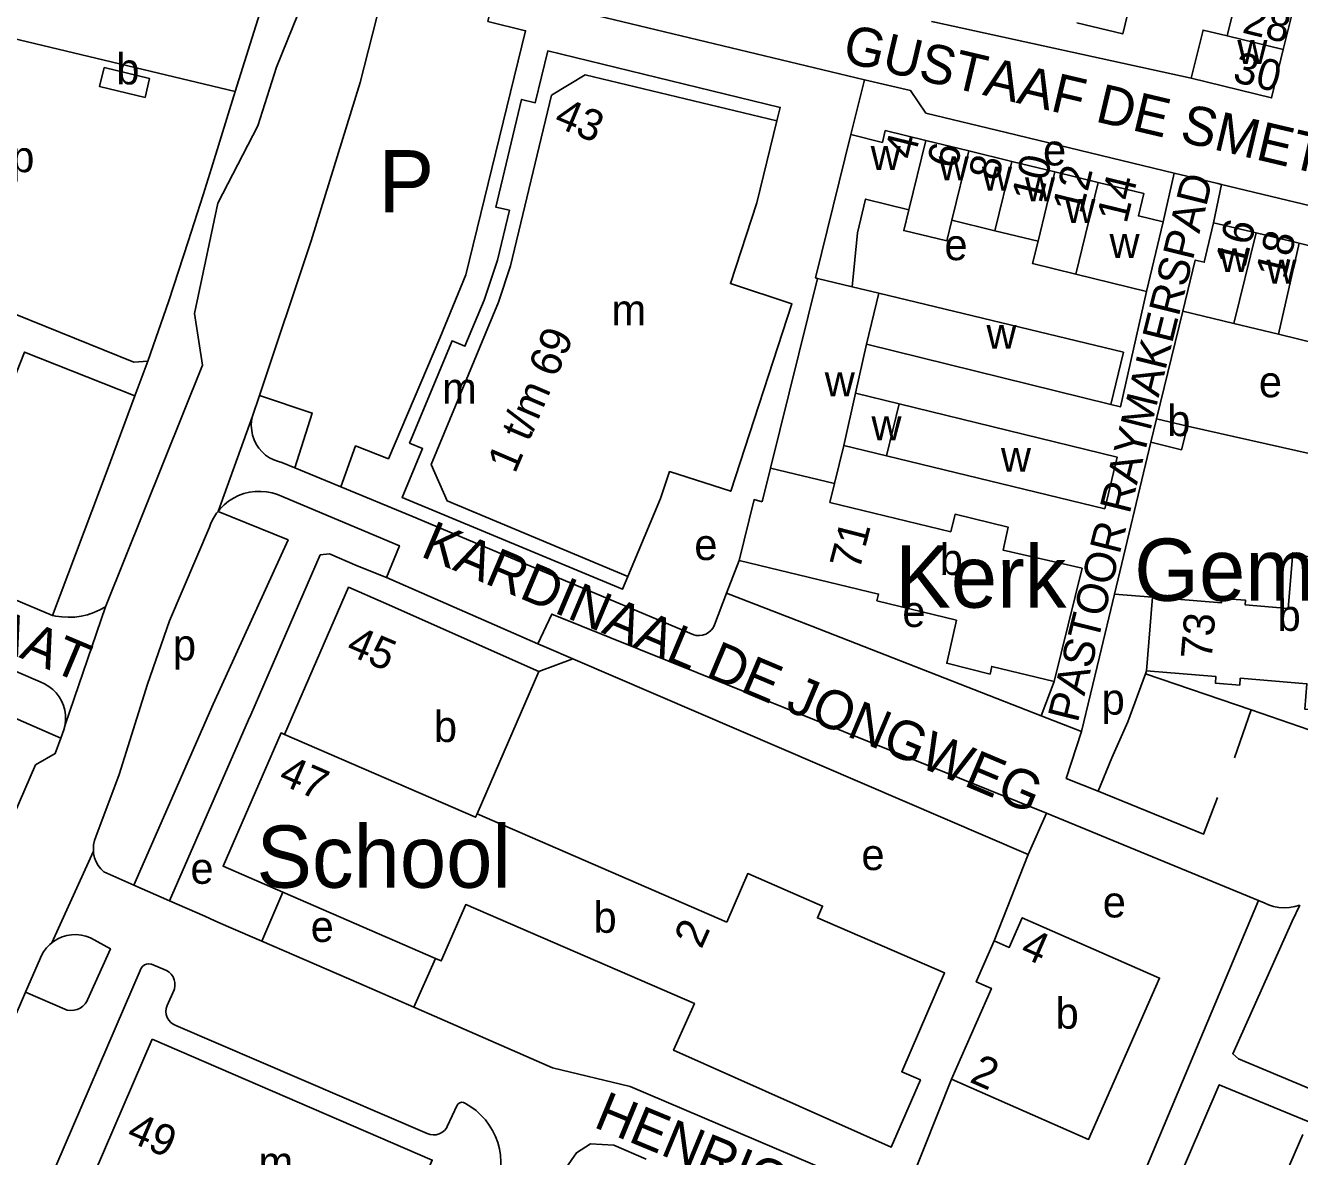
# Model space of a CAD drawing. Extents: x 162804 to 165059, y 381530 to 382901.
# Drawn here: x 163445.8 to 163609.5, y 381960.8 to 382106.1 of the extents above; entities that cross this region are included whole.
import ezdxf

# ---------------------------------------------------------------- set-up
doc = ezdxf.new("R2010")
doc.units = 0
for name, color, linetype in [('BLT_Basislijn', 7, 'Continuous'), ('BLT_Bebouwing', 7, 'Continuous'), ('BLT_Bebouwing_beschrifting', 7, 'Continuous'), ('BLT_Centroide', 7, 'Continuous'), ('BLT_Huisnummer', 7, 'Continuous'), ('BLT_Huisnummer_ tussenligend', 7, 'Continuous'), ('BLT_Huisnummer_reeks', 7, 'Continuous'), ('BLT_Onderdoorgang_en_onderverdeling', 7, 'Continuous'), ('BLT_Onderverdeling_panden', 7, 'Continuous'), ('BLT_Straatnaam', 7, 'Continuous'), ('BLT_Straatnaam_verkleind', 7, 'Continuous'), ('BLT_Tekst_parkeren', 7, 'Continuous'), ('BLT_Vlakafsluiter', 7, 'Continuous')]:
    doc.layers.add(name, color=color, linetype=linetype)

msp = doc.modelspace()

# ---------------------------------------------------------------- linework, layer by layer
at = {"layer": 'BLT_Basislijn'}
for p, q in [((163476.1, 382108.36), (163472.75, 382097.61)), ((163553.62, 382099.14), (163517.21, 382107.85)), ((163432.58, 382107.21), (163472.75, 382097.61)), ((163553.62, 382099.14), (163551.85, 382092.11)), ((163472.75, 382097.61), (163469.68, 382087.77)), ((163469.68, 382087.77), (163468.62, 382084.33)), ((163593.42, 382087.15), (163592.01, 382080.87)), ((163599.5, 382085.69), (163598.5, 382080.75)), ((163468.62, 382084.33), (163466.68, 382078.33)), ((163594.54, 382069.39), (163591.15, 382055.58)), ((163461.51, 382062.99), (163459.84, 382058.5)), ((163474.97, 382055.92), (163475.85, 382058.56)), ((163595.14, 382054.6), (163659.51, 382040.2)), ((163585.76, 382033.03), (163590.42, 382052.56)), ((163478.72, 382049.96), (163480.39, 382049.27)), ((163480.39, 382049.27), (163486.32, 382046.81)), ((163486.32, 382046.81), (163495.44, 382043.03)), ((163531.67, 382027.81), (163495.44, 382043.03)), ((163447.67, 382021.74), (163404.98, 382040.15)), ((163537.52, 382037.37), (163535.89, 382033.15)), ((163492.17, 382035.15), (163511.62, 382026.66)), ((163534.35, 382029.08), (163535.89, 382033.15)), ((163583.84, 382024.98), (163585.76, 382033.03)), ((163590.65, 382032.63), (163585.76, 382033.03)), ((163511.75, 382023.1), (163516.13, 382024.71)), ((163516.13, 382024.71), (163574.65, 381999.55)), ((163583.84, 382024.98), (163581.52, 382015.38)), ((163603.34, 382018.17), (163589.74, 382022.79)), ((163578.02, 382021.79), (163576.32, 382017.41)), ((163469.89, 382018.89), (163459.71, 381995.63)), ((163441.79, 382018.23), (163450.32, 382014.5)), ((163576.32, 382017.41), (163581.52, 382015.38)), ((163601.19, 382011.98), (163603.34, 382018.17)), ((163603.34, 382018.17), (163616.28, 382013.68)), ((163474.46, 382016.89), (163464.28, 381993.61)), ((163574.65, 381999.55), (163577.01, 382004.89)), ((163604.25, 381993.64), (163577.01, 382004.89)), ((163574.65, 381999.55), (163570.29, 381988.48)), ((163455.87, 381997.33), (163459.71, 381995.63)), ((163459.71, 381995.63), (163464.28, 381993.61)), ((163478.86, 381994.73), (163476.15, 381988.43)), ((163468.82, 381991.63), (163464.28, 381993.61)), ((163583.47, 381944.21), (163604.25, 381993.64)), ((163604.98, 381993.34), (163604.25, 381993.64)), ((163447.7, 381986.28), (163445.79, 381981.86)), ((163498.48, 381986.21), (163495.7, 381979.97)), ((163460.67, 381984.96), (163446.05, 381951.14)), ((163462, 381985.46), (163463.89, 381984.65)), ((163445.79, 381981.86), (163437.52, 381962.79)), ((163451.14, 381979.58), (163445.79, 381981.86)), ((163464.89, 381982.19), (163463.98, 381980.16)), ((163465.11, 381977.59), (163497.4, 381963.72)), ((163564.81, 381970.7), (163558.49, 381954.86)), ((163501.25, 381967.34), (163500, 381964.6))]:
    msp.add_line(p, q, dxfattribs=at)
for points in [[(163461.51, 382062.99), (163459.69, 382062.86), (163421.54, 382078.27), (163432.84, 382130.7), (163443.64, 382128.25), (163444.42, 382128.06), (163445.13, 382121.86)], [(163485.62, 382119.81), (163484.97, 382117.94), (163478.04, 382100.76), (163475.63, 382093.22), (163470.51, 382083.28), (163467.5, 382069.11), (163468.55, 382062.47), (163456.05, 382031.42)], [(163475.85, 382058.56), (163482.49, 382078.45), (163488.81, 382098.8), (163491.46, 382109.2)], [(163506.09, 382110.56), (163505.23, 382106.64), (163510.06, 382105.43), (163502.37, 382074.08), (163499.06, 382065.94), (163492.43, 382050.42), (163488.21, 382052.07), (163486.32, 382046.81)], [(163595.63, 382099.32), (163562.66, 382106.52), (163562.25, 382106.63)], [(163561.52, 382094.83), (163559.54, 382097.75), (163553.62, 382099.14)], [(163561.52, 382094.83), (163571.85, 382092.36), (163593.42, 382087.15)], [(163599.5, 382085.69), (163599.05, 382085.8), (163593.42, 382087.15)], [(163599.5, 382085.69), (163664.71, 382070.05), (163665.99, 382068.94), (163665.83, 382067.16), (163664.99, 382063.08)], [(163466.68, 382078.33), (163464.22, 382070.74), (163461.51, 382062.99)], [(163589.88, 382071.94), (163586.55, 382057.11), (163585.27, 382057.42)], [(163413.44, 382065.06), (163441.5, 382053.69), (163445.66, 382064.13), (163459.84, 382058.5)], [(163411.46, 382060.73), (163407.59, 382051.95), (163407.84, 382049.46), (163408.46, 382048.23), (163411.27, 382046.47), (163416.75, 382043.99), (163449.25, 382030.27)], [(163459.84, 382058.5), (163456.28, 382048.91), (163449.25, 382030.27)], [(163475.85, 382058.56), (163482.64, 382056.29), (163480.39, 382049.27)], [(163474.97, 382055.92), (163474.85, 382055.31), (163474.81, 382054.69), (163474.86, 382054.07), (163474.98, 382053.46), (163475.17, 382052.87), (163475.44, 382052.31), (163475.78, 382051.8), (163476.19, 382051.32), (163476.65, 382050.91), (163477.16, 382050.56), (163477.71, 382050.28), (163478.3, 382050.07), (163478.72, 382049.96)], [(163478.18, 382045.82), (163477.48, 382046.04), (163476.76, 382046.18), (163476.03, 382046.24), (163475.3, 382046.22), (163474.57, 382046.13), (163473.86, 382045.95), (163473.17, 382045.7), (163472.51, 382045.38), (163471.89, 382044.98), (163471.32, 382044.52), (163470.8, 382044), (163470.53, 382043.66)], [(163478.18, 382045.82), (163493.84, 382039.24), (163492.17, 382035.15)], [(163470.53, 382043.66), (163470.34, 382043.43), (163469.95, 382042.81), (163469.62, 382042.15), (163469.43, 382041.65)], [(163469.89, 382018.89), (163479.53, 382039.99), (163470.53, 382043.66)], [(163454.82, 382001.85), (163457.83, 382009.84), (163461.45, 382021.45), (163464.31, 382029.59), (163469.43, 382041.65)], [(163492.17, 382035.15), (163488.4, 382036.68), (163484.86, 382038.19), (163483.68, 382038.08), (163474.74, 382017.52), (163474.46, 382016.89)], [(163535.89, 382033.15), (163546.85, 382028.9), (163576.32, 382017.41)], [(163456.05, 382031.42), (163455.32, 382031.01), (163454.56, 382030.66), (163453.76, 382030.39), (163452.95, 382030.2), (163452.12, 382030.09), (163451.28, 382030.05), (163450.44, 382030.1), (163449.68, 382030.19), (163449.25, 382030.27)], [(163577.01, 382004.89), (163513.42, 382030.47), (163511.62, 382026.66)], [(163534.35, 382029.08), (163534.16, 382028.71), (163533.9, 382028.38), (163533.58, 382028.11), (163533.22, 382027.9), (163532.82, 382027.77), (163532.41, 382027.71), (163531.99, 382027.73), (163531.67, 382027.81)], [(163511.62, 382026.66), (163512.75, 382026.17), (163516.13, 382024.71)], [(163589.74, 382022.79), (163587.49, 382016.62), (163585.43, 382012.01), (163583.65, 382007.69)], [(163589.74, 382022.79), (163589.88, 382023.18)], [(163447.67, 382021.74), (163448.24, 382021.49), (163448.78, 382021.17), (163449.28, 382020.79), (163449.72, 382020.34), (163450.11, 382019.85), (163450.42, 382019.3), (163450.67, 382018.73), (163450.84, 382018.12), (163450.93, 382017.5), (163450.94, 382016.88), (163450.87, 382016.25)], [(163450.87, 382016.25), (163450.71, 382015.58)], [(163450.32, 382014.5), (163449.61, 382012.54), (163447.08, 382011.09), (163442.21, 382000)], [(163450.71, 382015.58), (163450.32, 382014.5)], [(163583.65, 382007.69), (163579.56, 382009.35), (163581.52, 382015.38)], [(163599.02, 382006.9), (163597.21, 382002.19), (163583.65, 382007.69)], [(163454.52, 381999.98), (163454.53, 382000.82), (163454.64, 382001.36), (163454.82, 382001.85)], [(163455.87, 381997.33), (163455.48, 381997.72), (163455.14, 381998.16), (163454.86, 381998.64), (163454.66, 381999.16), (163454.54, 381999.71), (163454.52, 381999.98)], [(163609.6, 381993.07), (163608.58, 381991), (163600.95, 381973.96), (163601.68, 381973.33), (163612.23, 381968.88)], [(163609.6, 381993.07), (163608.94, 381992.88), (163608.26, 381992.76), (163607.57, 381992.73), (163606.88, 381992.77), (163606.2, 381992.9), (163605.54, 381993.1), (163604.98, 381993.34)], [(163476.15, 381988.43), (163471.86, 381990.27), (163470.14, 381991.05), (163468.82, 381991.63)], [(163449.16, 381988.21), (163448.92, 381988.01), (163448.49, 381987.56), (163448.11, 381987.07), (163447.81, 381986.52), (163447.7, 381986.28)], [(163454.15, 381988.86), (163453.56, 381989.07), (163452.96, 381989.21), (163452.34, 381989.27), (163451.71, 381989.25), (163451.1, 381989.15), (163450.5, 381988.98), (163449.93, 381988.72), (163449.4, 381988.4), (163449.16, 381988.21)], [(163453.77, 381980.9), (163456.7, 381987.46), (163454.15, 381988.86)], [(163495.7, 381979.97), (163488.65, 381983.04), (163476.15, 381988.43)], [(163460.67, 381984.96), (163460.84, 381985.19), (163461.06, 381985.38), (163461.32, 381985.49), (163461.61, 381985.54), (163461.89, 381985.49), (163462, 381985.46)], [(163463.89, 381984.65), (163464.23, 381984.44), (163464.52, 381984.17), (163464.75, 381983.85), (163464.91, 381983.48), (163464.99, 381983.1), (163465, 381982.7), (163464.93, 381982.31), (163464.89, 381982.19)], [(163451.14, 381979.58), (163451.57, 381979.52), (163452, 381979.55), (163452.42, 381979.65), (163452.81, 381979.83), (163453.16, 381980.08), (163453.46, 381980.39), (163453.69, 381980.75), (163453.77, 381980.9)], [(163463.98, 381980.16), (163463.87, 381979.78), (163463.83, 381979.39), (163463.88, 381979), (163464, 381978.62), (163464.2, 381978.28), (163464.46, 381977.99), (163464.77, 381977.75), (163465.11, 381977.59)], [(163558.49, 381954.86), (163523.49, 381969.76), (163513.52, 381972.17), (163497.69, 381979.1), (163495.7, 381979.97)], [(163610.67, 381965.27), (163599.23, 381969.98), (163587.41, 381942.48)], [(163501.25, 381967.34), (163501.4, 381967.53), (163501.61, 381967.66), (163501.85, 381967.72), (163502.09, 381967.7), (163502.33, 381967.59)], [(163502.33, 381967.59), (163503.04, 381967.15), (163503.71, 381966.65), (163504.33, 381966.09), (163504.9, 381965.47), (163505.4, 381964.8), (163505.83, 381964.08), (163506.2, 381963.33), (163506.49, 381962.55), (163506.7, 381961.74), (163506.84, 381960.91), (163506.9, 381960.07), (163506.88, 381959.24), (163506.77, 381958.41), (163506.59, 381957.59), (163506.53, 381957.37)], [(163497.4, 381963.72), (163497.78, 381963.59), (163498.18, 381963.53), (163498.57, 381963.56), (163498.96, 381963.67), (163499.31, 381963.85), (163499.62, 381964.1), (163499.88, 381964.4), (163500, 381964.6)], [(163607.08, 381942.55), (163601.81, 381944.83), (163609.95, 381963.6)], [(163525.56, 381960.4), (163521.39, 381962.23), (163518.39, 381962.39), (163516.59, 381961.24), (163514.54, 381958.29), (163509.04, 381945.63)]]:
    msp.add_lwpolyline(points, dxfattribs=at)
at = {"layer": 'BLT_Bebouwing'}
for p, q in [((163600.25, 382104.77), (163601.77, 382110.97)), ((163608.98, 382109.21), (163607.46, 382103.01)), ((163555.94, 382091.09), (163551.85, 382092.11)), ((163567.03, 382089.99), (163561.49, 382091.34)), ((163572.56, 382088.65), (163567.03, 382089.99)), ((163578.11, 382087.3), (163572.56, 382088.65)), ((163583.65, 382085.95), (163578.11, 382087.3)), ((163564.86, 382081.09), (163570.4, 382079.74)), ((163570.4, 382079.74), (163575.94, 382078.4)), ((163589.88, 382071.94), (163592.01, 382080.87)), ((163603.95, 382079.47), (163598.5, 382080.75)), ((163609.49, 382078.12), (163603.95, 382079.47)), ((163615.02, 382076.77), (163609.49, 382078.12)), ((163601.11, 382067.8), (163594.54, 382069.39)), ((163606.82, 382066.43), (163601.11, 382067.8)), ((163590.42, 382052.56), (163591.15, 382055.58)), ((163591.15, 382055.58), (163595.14, 382054.6)), ((163590.65, 382032.63), (163589.88, 382023.18))]:
    msp.add_line(p, q, dxfattribs=at)
for points in [[(163582.59, 382113.84), (163588.57, 382112.38), (163588, 382109.89), (163586.83, 382105.03), (163580.9, 382106.45)], [(163595.63, 382099.32), (163597.15, 382105.53), (163600.25, 382104.77)], [(163523.21, 382035.28), (163522.53, 382033.65), (163494.18, 382045.43), (163496.82, 382051.73), (163495.15, 382052.45), (163500.62, 382065.6), (163502.26, 382064.88), (163504.76, 382070.83), (163506.44, 382075.94), (163507.99, 382082.36), (163506.23, 382082.77), (163509.54, 382096.61), (163511.31, 382096.19), (163512.91, 382102.84), (163542.79, 382095.58), (163542.36, 382093.85)], [(163607.46, 382103.01), (163605.95, 382096.8), (163595.63, 382099.32)], [(163455.9, 382100.72), (163455.31, 382098.26), (163461.15, 382096.87), (163461.73, 382099.28), (163455.9, 382100.72)], [(163542.36, 382093.85), (163539.8, 382083.34), (163536.4, 382072.95), (163544.3, 382070.36), (163536.43, 382046.25), (163528.57, 382048.79), (163527.39, 382045.3), (163523.21, 382035.28)], [(163555.94, 382091.09), (163556.3, 382092.6), (163561.49, 382091.34)], [(163551.85, 382092.11), (163547.34, 382073.66), (163547.57, 382073.61)], [(163592.01, 382080.87), (163588.83, 382081.64), (163589.53, 382084.52), (163583.65, 382085.95)], [(163552.06, 382072.52), (163552.71, 382079.45), (163553.77, 382083.8), (163559.32, 382082.43)], [(163559.32, 382082.43), (163558.67, 382079.76), (163564.21, 382078.42), (163564.86, 382081.09)], [(163594.54, 382069.39), (163596.13, 382075.97), (163597.29, 382075.69), (163598.5, 382080.75)], [(163575.94, 382078.4), (163575.23, 382075.51), (163580.78, 382074.16)], [(163547.57, 382073.61), (163541.53, 382049.21)], [(163580.78, 382074.16), (163589.88, 382071.94)], [(163555.49, 382071.7), (163552.06, 382072.52)], [(163585.27, 382057.42), (163586.9, 382064.11), (163555.49, 382071.7)], [(163612.86, 382067.86), (163612.23, 382065.12), (163606.82, 382066.43)], [(163552.48, 382058.86), (163553.89, 382065.14)], [(163553.89, 382065.14), (163585.27, 382057.42)], [(163558.07, 382057.49), (163552.48, 382058.86)], [(163556.44, 382050.81), (163584.51, 382044), (163586.11, 382050.62), (163558.07, 382057.49)], [(163595.14, 382054.6), (163594.39, 382051.58), (163590.42, 382052.56)], [(163549.76, 382047.23), (163550.95, 382052.14)], [(163550.95, 382052.14), (163556.44, 382050.81)], [(163541.53, 382049.21), (163540.47, 382044.9)], [(163549.17, 382044.8), (163549.75, 382047.23)], [(163644.93, 382018.36), (163622.93, 382027.73), (163625.55, 382033.89), (163621.91, 382034.8), (163624.39, 382044.73), (163615.32, 382047), (163612.89, 382037.28), (163608.67, 382038.34), (163608.08, 382031.19), (163602.56, 382031.64), (163602.61, 382032.24), (163599.56, 382032.49), (163599.51, 382031.9), (163590.65, 382032.63)], [(163540.47, 382044.9), (163539.43, 382045.18), (163537.52, 382037.37)], [(163564.71, 382041.03), (163549.17, 382044.8)], [(163578.02, 382021.79), (163581.59, 382036.35), (163571.45, 382038.7), (163572.08, 382041.64), (163565.26, 382043.3), (163564.71, 382041.03)], [(163537.52, 382037.37), (163555.43, 382033.04), (163555.22, 382032.17), (163565.44, 382029.68)], [(163479.09, 382015), (163487.31, 382033.91), (163491.78, 382031.96), (163511.75, 382023.1)], [(163565.44, 382029.68), (163564.19, 382024.14), (163569.77, 382022.76), (163569.99, 382023.74), (163578.02, 382021.79)], [(163511.75, 382023.1), (163503.83, 382004.78)], [(163589.88, 382023.18), (163598.8, 382022.44), (163598.73, 382021.6), (163601.85, 382021.35), (163601.92, 382022.22), (163610.49, 382021.51), (163610.22, 382018.25), (163611.58, 382018.14)], [(163478.86, 381994.73), (163471.19, 381998.07), (163478.64, 382015.2), (163479.09, 382015)], [(163535.92, 381990.89), (163503.83, 382004.78)], [(163498.48, 381986.21), (163499.22, 381985.89), (163502.37, 381993.13), (163531.76, 381980.41), (163529.09, 381974.41), (163557.07, 381961.96), (163560.81, 381970.61), (163558.42, 381971.64), (163563.93, 381984.35), (163547.57, 381991.43), (163548.23, 381992.94), (163538.61, 381997.11), (163535.92, 381990.89)], [(163498.48, 381986.21), (163478.86, 381994.73)], [(163570.29, 381988.48), (163572.23, 381987.63), (163573.91, 381991.45), (163591.55, 381983.69), (163582.44, 381962.95), (163564.81, 381970.7)], [(163564.81, 381970.7), (163569.93, 381982.36), (163567.98, 381983.21), (163570.29, 381988.48)], [(163462.08, 381975.82), (163453.42, 381955.76), (163489.4, 381940.24), (163498.06, 381960.3), (163462.08, 381975.82)]]:
    msp.add_lwpolyline(points, dxfattribs=at)
at = {"layer": 'BLT_Onderdoorgang_en_onderverdeling'}
for points in [[(163506.59, 382070.57), (163508.11, 382075.23), (163513.39, 382097.14), (163517.71, 382099.79), (163542.36, 382093.85)], [(163523.21, 382035.28), (163500, 382045), (163497.93, 382049.69), (163506.59, 382070.57)]]:
    msp.add_lwpolyline(points, dxfattribs=at)
at = {"layer": 'BLT_Onderverdeling_panden'}
for p, q in [((163607.46, 382103.01), (163600.25, 382104.77)), ((163559.32, 382082.43), (163561.49, 382091.34)), ((163564.86, 382081.09), (163567.03, 382089.99)), ((163570.4, 382079.74), (163572.56, 382088.65)), ((163575.94, 382078.4), (163578.11, 382087.3)), ((163580.78, 382074.16), (163583.65, 382085.95)), ((163601.11, 382067.8), (163603.95, 382079.47)), ((163606.82, 382066.43), (163609.49, 382078.12)), ((163552.06, 382072.52), (163547.57, 382073.61)), ((163553.89, 382065.14), (163555.49, 382071.7)), ((163550.95, 382052.14), (163552.48, 382058.86)), ((163558.07, 382057.49), (163556.44, 382050.81)), ((163549.76, 382047.23), (163541.53, 382049.21))]:
    msp.add_line(p, q, dxfattribs=at)
msp.add_lwpolyline([(163479.09, 382015), (163503.64, 382004.35), (163503.83, 382004.78)], dxfattribs=at)
at = {"layer": 'BLT_Vlakafsluiter'}
for p, q in [((163470.53, 382043.66), (163474.97, 382055.92)), ((163450.87, 382016.25), (163456.05, 382031.42)), ((163449.16, 381988.21), (163454.52, 381999.98))]:
    msp.add_line(p, q, dxfattribs=at)

# ---------------------------------------------------------------- texts
at = {"layer": 'BLT_Bebouwing_beschrifting'}
for s, p in [('Gemeenschapshuis', (163588.3, 382032.17)), ('Kerk', (163557.59, 382031.29)), ('School', (163475.47, 381995.3))]:
    msp.add_text(s, height=8, dxfattribs=at).set_placement(p)
at = {"layer": 'BLT_Centroide'}
for s, p in [('w', (163601.55, 382101.16)), ('b', (163457.46, 382098.54)), ('e', (163576.57, 382088.12)), ('p', (163443.95, 382087.26)), ('w', (163554.42, 382087.55)), ('w', (163563.17, 382086.22)), ('w', (163568.72, 382084.88)), ('w', (163574.25, 382083.53)), ('w', (163579.44, 382080.72)), ('e', (163563.9, 382075.95)), ('w', (163585.12, 382076.24)), ('w', (163599.25, 382074.41)), ('w', (163605.3, 382072.95)), ('m', (163521.11, 382067.56)), ('w', (163569.3, 382064.56)), ('w', (163548.52, 382058.45)), ('e', (163604.32, 382058.33)), ('m', (163499.34, 382057.49)), ('b', (163592.54, 382053.34)), ('w', (163554.52, 382052.81)), ('w', (163571.16, 382048.75)), ('e', (163531.75, 382037.41)), ('b', (163563.3, 382035.5)), ('b', (163606.73, 382028.31)), ('e', (163558.49, 382028.81)), ('p', (163464.73, 382024.53)), ('p', (163584.11, 382017.55)), ('b', (163498.28, 382014.03)), ('e', (163553.23, 381997.57)), ('e', (163466.99, 381995.8)), ('e', (163584.25, 381991.48)), ('b', (163518.8, 381989.51)), ('e', (163482.44, 381988.33)), ('b', (163578.19, 381977.19)), ('m', (163475.74, 381958.03))]:
    msp.add_text(s, height=4, dxfattribs=at).set_placement(p)
at = {"layer": 'BLT_Huisnummer'}
for s, rotation, p in [('30', 346.2746, (163600.81, 382098.92)), ('4', 76.3205, (163560.04, 382088.75)), ('8', 76.3205, (163570.82, 382085.99)), ('14', 76.3205, (163587.31, 382080.55)), ('16', 76.322, (163602.55, 382074.83)), ('71', 75.5193, (163552.96, 382035.97)), ('45', 336.9149, (163486.81, 382025.4)), ('49', 336.6626, (163458.58, 381962.88))]:
    msp.add_text(s, height=4, rotation=rotation, dxfattribs=at).set_placement(p)
at = {"layer": 'BLT_Huisnummer_ tussenligend'}
for s, rotation, p in [('28', 346.2839, (163602.04, 382105.22)), ('6', 76.3205, (163565.47, 382087.55)), ('10', 76.3205, (163576.35, 382083.13)), ('12', 76.3205, (163581.6, 382081.76)), ('18', 76.322, (163607.73, 382073.37))]:
    msp.add_text(s, height=4, rotation=rotation, dxfattribs=at).set_placement(p)
at = {"layer": 'BLT_Huisnummer_reeks'}
for s, rotation, p in [('43', 337.27, (163513.53, 382093.27)), ('1 t/m 69', 66.7851, (163508.7, 382048.41)), ('73', 85.3061, (163598.25, 382024.54)), ('47', 336.5162, (163478.12, 382008.78)), ('2', 66.0141, (163532.66, 381987.32)), ('4', 336.2726, (163573.46, 381986.54)), ('2', 336.272, (163566.99, 381970.39))]:
    msp.add_text(s, height=4, rotation=rotation, dxfattribs=at).set_placement(p)
at = {"layer": 'BLT_Straatnaam'}
for s, rotation, p in [('GUSTAAF DE SMETSTRAAT', 346.724, (163550.61, 382101.48)), ('ENSORSTRAAT', 337.1747, (163406.49, 382041.09)), ('KARDINAAL DE JONGWEG', 337.1246, (163496.41, 382037.95)), ('HENRICUS HERPSTRAAT', 337.5512, (163518.65, 381964.6))]:
    msp.add_text(s, height=5, rotation=rotation, dxfattribs=at).set_placement(p)
at = {"layer": 'BLT_Straatnaam_verkleind'}
msp.add_text('PASTOOR RAYMAKERSPAD', height=4, rotation=76.0241, dxfattribs=at).set_placement((163581.02, 382016.4))
at = {"layer": 'BLT_Tekst_parkeren'}
msp.add_text('P', height=8, dxfattribs=at).set_placement((163491.18, 382082.09))

doc.saveas('drawing.dxf')
